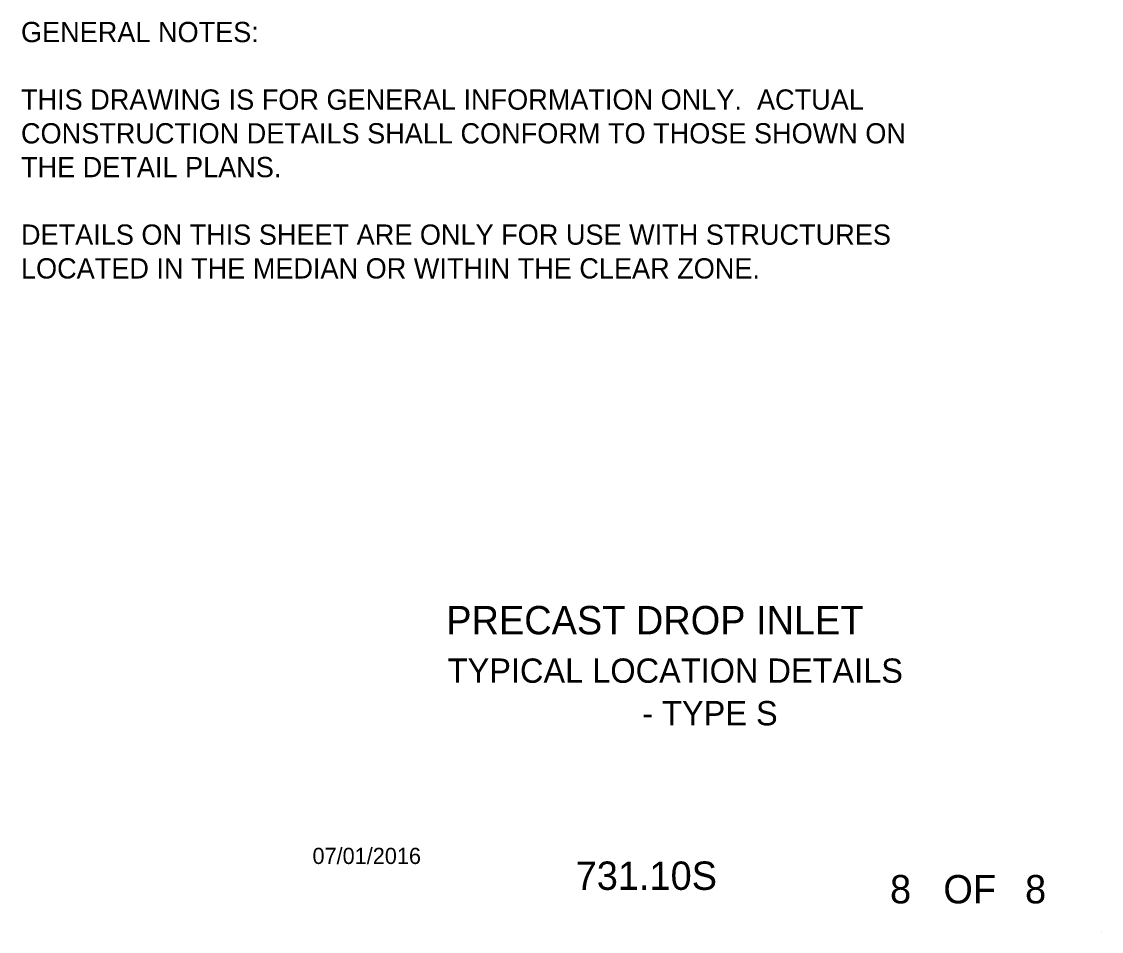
# Model space of a CAD drawing. Extents: x -437.4 to -407.9, y -458.1 to -438.
# Drawn here: x -415.85 to -407.86, y -458.05 to -451.31 of the extents above; entities that cross this region are included whole.
import ezdxf

# ---------------------------------------------------------------- set-up
doc = ezdxf.new("R2010")
doc.units = 0
for name, color, linetype in [('Common-Notes', 7, 'Continuous'), ('Level 4', 7, 'Continuous'), ('Level 45', 7, 'Continuous')]:
    doc.layers.add(name, color=color, linetype=linetype)

msp = doc.modelspace()

# ---------------------------------------------------------------- linework, layer by layer
at = {"layer": 'Level 4'}
msp.add_line((-407.859, -458.0508), (-407.859, -458.0508), dxfattribs=at)
msp.add_line((-407.859, -458.0508), (-407.859, -458.0508), dxfattribs=at)
msp.add_line((-407.859, -458.0508), (-407.859, -458.0508), dxfattribs=at)
msp.add_line((-407.859, -458.0508), (-407.859, -458.0508), dxfattribs=at)
msp.add_line((-407.859, -458.0508), (-407.859, -458.0508), dxfattribs=at)
msp.add_line((-407.859, -458.0508), (-407.859, -458.0508), dxfattribs=at)
msp.add_line((-407.859, -458.0508), (-407.859, -458.0508), dxfattribs=at)
msp.add_line((-407.859, -458.0508), (-407.859, -458.0508), dxfattribs=at)

# ---------------------------------------------------------------- texts
at = {"layer": 'Common-Notes'}
for s, height, p in [('PRECAST DROP INLET', 0.21, (-412.7101, -455.8514)), ('TYPICAL LOCATION DETAILS', 0.18, (-412.6992, -456.2101)), ('- TYPE S', 0.18, (-411.2592, -456.5251)), ('731.10S', 0.21, (-411.7516, -457.7433)), ('8', 0.21, (-409.4242, -457.8433)), ('OF', 0.21, (-409.0292, -457.8433)), ('8', 0.21, (-408.4242, -457.8433))]:
    msp.add_text(s, height=height, dxfattribs=at).set_placement(p)
at = {"layer": 'Level 4'}
msp.add_text('07/01/2016', height=0.12, dxfattribs=at).set_placement((-413.7005, -457.5518))
at = {"layer": 'Level 45'}
for s, p in [('GENERAL NOTES:', (-415.8591, -451.4665)), ('THIS DRAWING IS FOR GENERAL INFORMATION ONLY.  ACTUAL ', (-415.8591, -451.9665)), ('CONSTRUCTION DETAILS SHALL CONFORM TO THOSE SHOWN ON ', (-415.8591, -452.2165)), ('THE DETAIL PLANS.', (-415.8591, -452.4665)), ('DETAILS ON THIS SHEET ARE ONLY FOR USE WITH STRUCTURES ', (-415.8591, -452.9665)), ('LOCATED IN THE MEDIAN OR WITHIN THE CLEAR ZONE.', (-415.8591, -453.2165))]:
    msp.add_text(s, height=0.15, dxfattribs=at).set_placement(p)

doc.saveas('drawing.dxf')
